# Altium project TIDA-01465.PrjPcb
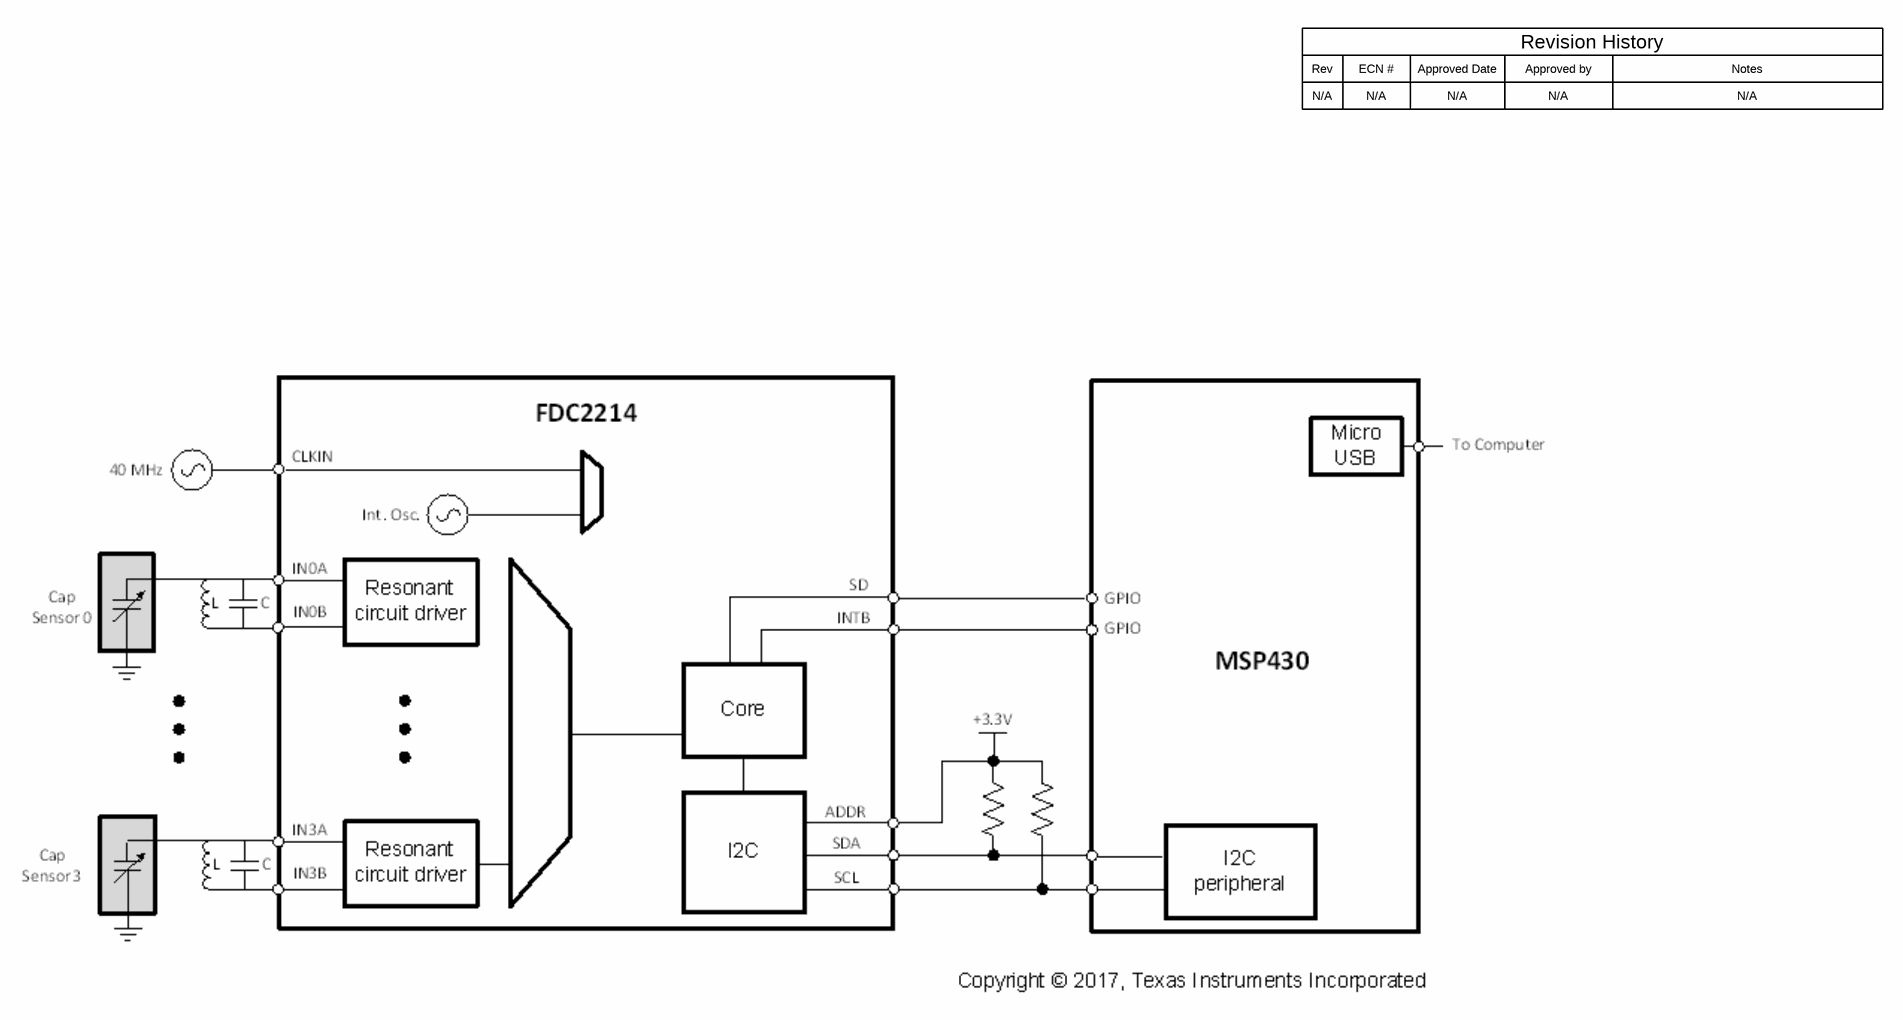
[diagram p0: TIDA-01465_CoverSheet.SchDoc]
CopyrightYear: 2016; PCB_Layout: Who did the Layout?; PCB_Rev: E1; PRJ_Customer: Public Release; PRJ_Engineer: Richard Wang; PRJ_Number: TIDA-01465; PRJ_Orderable: Orderable; PRJ_Title: Frost and ice detection; SCH_Rev: E1; TechSupport: http://www.ti.com/support; TID: TIDA-01465
3 sheets, 111 parts. Net scope: global (net labels, ports and power ports of the same name join across sheets).
Board file: TIDA-01465_PCB.PcbDoc
Sheets:
  TIDA-01465_CoverSheet.SchDoc
  TIDA-01465_Hardware.SchDoc
  TIDA-01465_Main.SchDoc

## Sheet TIDA-01465_CoverSheet.SchDoc
size 431 x 279 mm; Date: Not shown in title block; ApprovedBy: Not shown in title block; CheckedBy: Not shown in title block; Author: Not shown in title block; CompanyName: Not shown in title block; DrawnBy: Richard Wang; Engineer: Richard Wang; Organization: Not shown in title block; Address1: Not shown in title block; Address2: Not shown in title block; Address3: Not shown in title block; Address4: Not shown in title block; DocumentNumber: 1; Revision: Use project parameter SCH_Rev; SheetNumber: 1; SheetTotal: 3; PageSetup: Record=PageOptions¦CenterHorizontal=True¦CenterVertical=True¦PrintScale=1.00¦XCorrection=1.00¦YCorrection=1.00¦PrintKind=0¦BorderSize=5000000¦LeftOffset=0¦BottomOffset=0¦Orientation=2¦PaperLength=1000¦PaperWidth=1000¦Scale=100¦PaperSource=15¦PrintQuality=600¦MediaType=1¦DitherType=10¦PaperKind=Letter¦PrintScaleMode=1

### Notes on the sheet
- Rev
- N/A
- ECN #
- Approved Date
- Approved by
- Revision History
- Notes

## Sheet TIDA-01465_Hardware.SchDoc
size 431 x 279 mm; Date: Not shown in title block; ApprovedBy: Not shown in title block; CheckedBy: Not shown in title block; Author: Not shown in title block; CompanyName: Not shown in title block; Engineer: Not shown in title block; Organization: Not shown in title block; Address1: Not shown in title block; Address2: Not shown in title block; Address3: Not shown in title block; Address4: Not shown in title block; DocumentNumber: 1; Revision: Use project parameter SCH_Rev; SheetNumber: 3; SheetTotal: 3; PageSetup: Record=PageOptions¦CenterHorizontal=True¦CenterVertical=True¦PrintScale=1.00¦XCorrection=1.00¦YCorrection=1.00¦PrintKind=0¦BorderSize=5000000¦LeftOffset=0¦BottomOffset=0¦Orientation=2¦PaperLength=1000¦PaperWidth=1000¦Scale=100¦PaperSource=15¦PrintQuality=600¦MediaType=1¦DitherType=10¦PaperKind=Letter¦PrintScaleMode=1
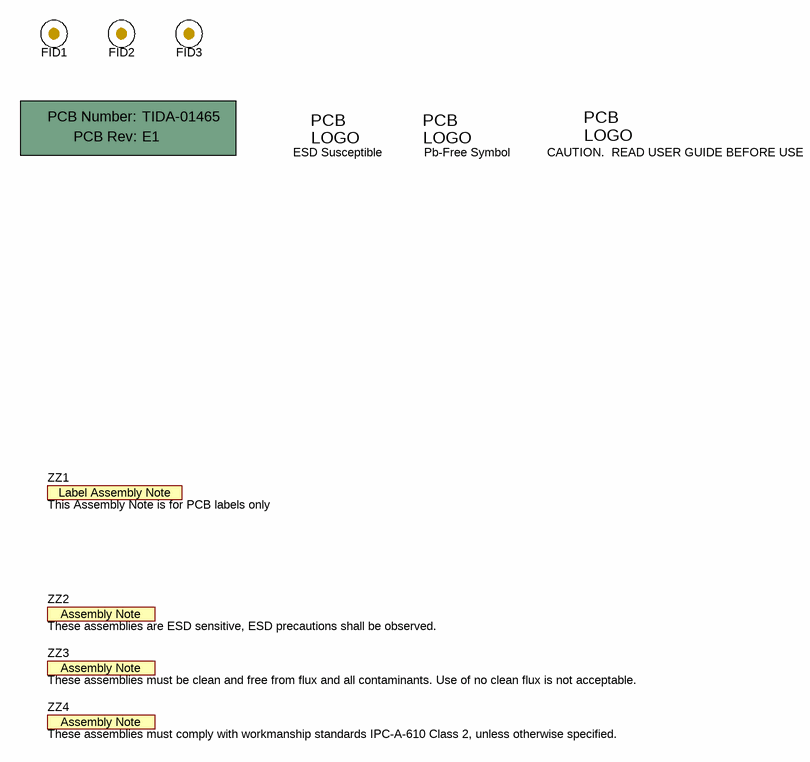
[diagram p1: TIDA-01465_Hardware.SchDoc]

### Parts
!PCB  Printed Circuit Board  (value not drawn)  (mechanical)
FID1  Fiducial  [Fiducial10-20]  (value not drawn)
FID2  Fiducial  [Fiducial10-20]  (value not drawn)
FID3  Fiducial  [Fiducial10-20]  (value not drawn)
Logo2  CAUTION.  READ USER GUIDE BEFORE USE  [IEC_Caution_Small]  (no BOM)
Logo3  Pb-Free Symbol  [Pb-Free_Overlay_Medium]  (no BOM)
Logo4  ESD Susceptible  [ESD_Overlay_Small]  (no BOM)
ZZ1  This Assembly Note is for PCB labels only  [AssemblyNoteLabel]  (no BOM)
ZZ2  These assemblies are ESD sensitive, ESD precautions shall be observed.  [AssemblyNote]  (no BOM)
ZZ3  These assemblies must be clean and free from flux and all contaminants. Use of no clean flux is not acceptable.  [AssemblyNote]  (no BOM)
ZZ4  These assemblies must comply with workmanship standards IPC-A-610 Class 2, unless otherwise specified.  [AssemblyNote]  (no BOM)

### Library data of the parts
!PCB = PCB: Manufacturer: Any; PartNumber: TIDA-01467; SymbolCreator: a0412235
FID1-FID3 = Fiducial: Fiducial mark.  There is nothing to buy or mount.; SymbolCreator: codlsc
Logo2 = IEC_Caution: IEC 61010-1 Caution Warning; SymbolCreator: a0412235
Logo3 = Pb-Free: SymbolCreator: a0412235
Logo4 = ESD_Susceptible: ESD Susceptible Symbol; SymbolCreator: a0412235
ZZ1 = AssemblyNoteLabel: SymbolCreator: a0412235
ZZ2-ZZ4 = AssemblyNote: SymbolCreator: codlsc

## Sheet TIDA-01465_Main.SchDoc
size 431 x 279 mm; Date: Not shown in title block; ApprovedBy: Not shown in title block; CheckedBy: Not shown in title block; Author: Not shown in title block; CompanyName: Not shown in title block; DrawnBy: Richard Wang; Engineer: Richard Wang; Organization: Not shown in title block; Address1: Not shown in title block; Address2: Not shown in title block; Address3: Not shown in title block; Address4: Not shown in title block; DocumentNumber: 1; Revision: Use project parameter SCH_Rev; SheetNumber: 2; SheetTotal: 3; PageSetup: Record=PageOptions¦CenterHorizontal=True¦CenterVertical=True¦PrintScale=1.00¦XCorrection=1.00¦YCorrection=1.00¦PrintKind=0¦BorderSize=5000000¦LeftOffset=0¦BottomOffset=0¦Orientation=2¦PaperLength=1000¦PaperWidth=1000¦Scale=100¦PaperSource=15¦PrintQuality=600¦MediaType=1¦DitherType=10¦PaperKind=Letter¦PrintScaleMode=1
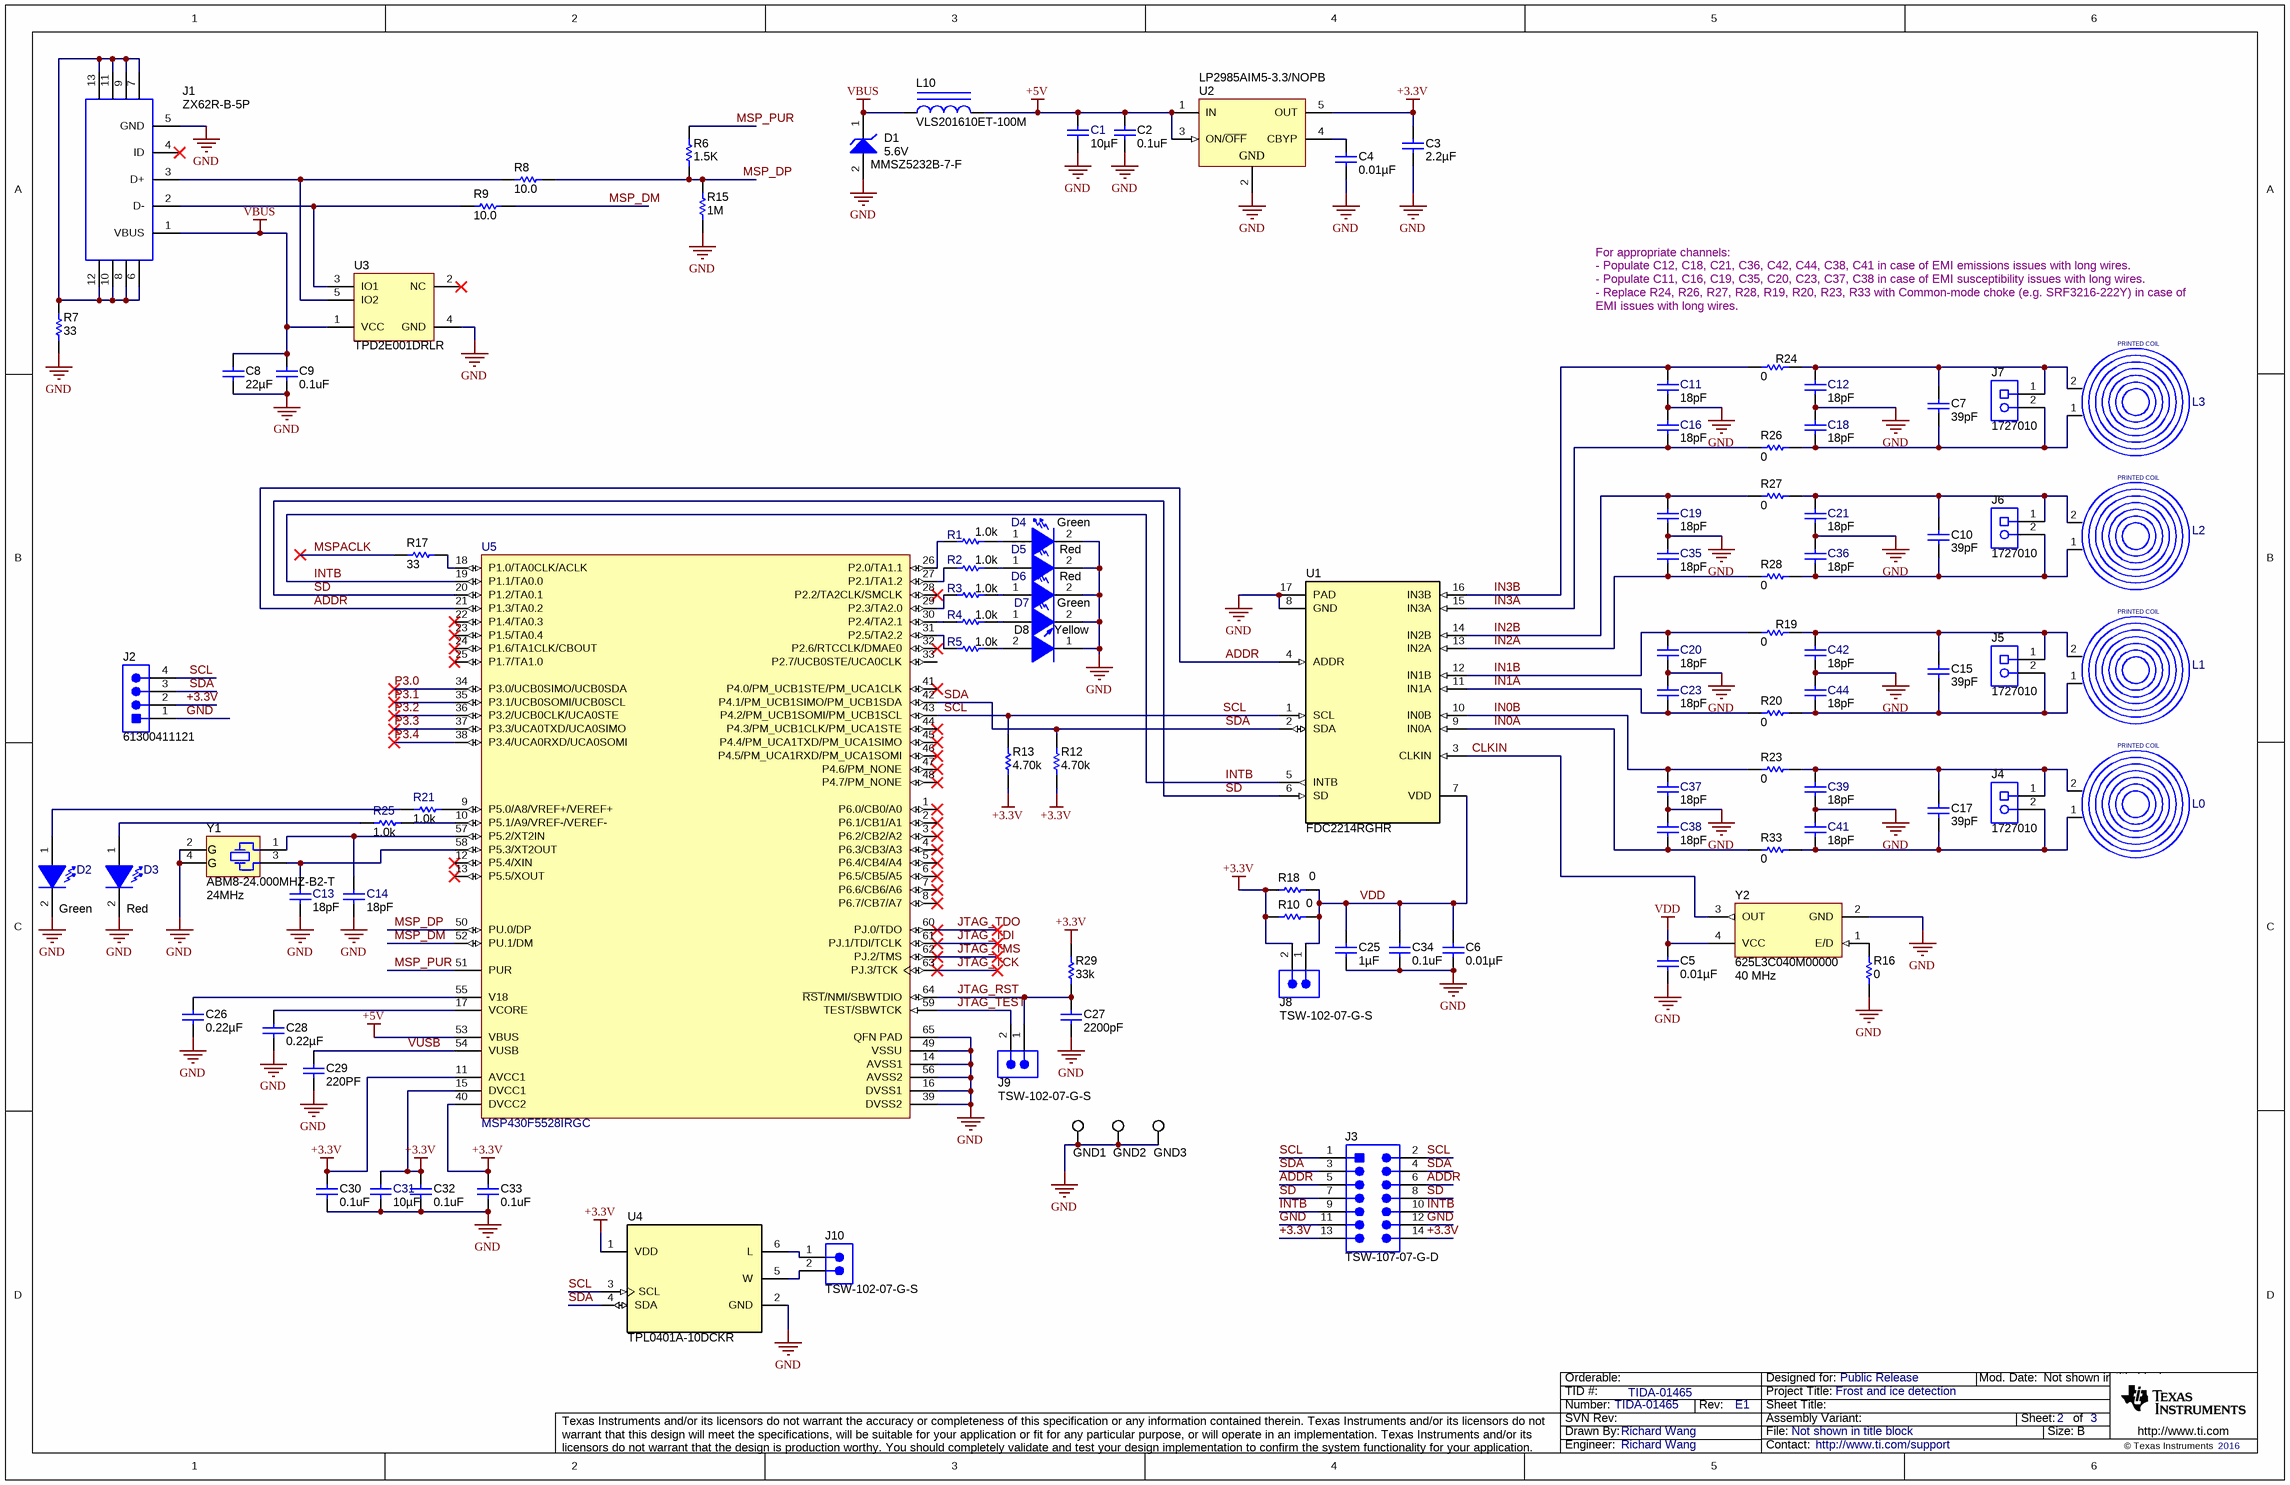
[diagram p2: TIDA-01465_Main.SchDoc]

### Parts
C1  ValueDisplayed: 10µF  [0603]  (hidden comment: C1608X5R1A106M)
C2  value 0.1uF  [0402]  (hidden comment: GRM155R71C104JA88D)
C3  ValueDisplayed: 2.2µF  [0603]  (hidden comment: C0603C225K8PACTU)
C4  ValueDisplayed: 0.01µF  [0603]  (hidden comment: C1608C0G1E103J)
C5  ValueDisplayed: 0.01µF  [0603]  (hidden comment: C1608C0G1E103J)
C6  ValueDisplayed: 0.01µF  [0402]  (hidden comment: C1005X7R1C103K)
C7  ValueDisplayed: 39pF  [0603]  (hidden comment: 06035A390JAT2A)
C8  ValueDisplayed: 22µF  [0805_HV]  (hidden comment: C2012X5R1C226K125AC)
C9  value 0.1uF  [0402]  (hidden comment: GRM155R71C104JA88D)
C10  ValueDisplayed: 39pF  [0603]  (hidden comment: 06035A390JAT2A)
C11  ValueDisplayed: 18pF  [0603]  (hidden comment: GRM1885C2A180JA01D)
C12  ValueDisplayed: 18pF  [0603]  (hidden comment: GRM1885C2A180JA01D)
C13  ValueDisplayed: 18pF  [0603]  (hidden comment: GRM1885C2A180JA01D)
C14  ValueDisplayed: 18pF  [0603]  (hidden comment: GRM1885C2A180JA01D)
C15  ValueDisplayed: 39pF  [0603]  (hidden comment: 06035A390JAT2A)
C16  ValueDisplayed: 18pF  [0603]  (hidden comment: GRM1885C2A180JA01D)
C17  ValueDisplayed: 39pF  [0603]  (hidden comment: 06035A390JAT2A)
C18  ValueDisplayed: 18pF  [0603]  (hidden comment: GRM1885C2A180JA01D)
C19  ValueDisplayed: 18pF  [0603]  (hidden comment: GRM1885C2A180JA01D)
C20  ValueDisplayed: 18pF  [0603]  (hidden comment: GRM1885C2A180JA01D)
C21  ValueDisplayed: 18pF  [0603]  (hidden comment: GRM1885C2A180JA01D)
C23  ValueDisplayed: 18pF  [0603]  (hidden comment: GRM1885C2A180JA01D)
C25  ValueDisplayed: 1µF  [0402]  (hidden comment: GRM155R61A105KE15D)
C26  ValueDisplayed: 0.22µF  [0805_HV]  (hidden comment: 08053C224JAT2A)
C27  ValueDisplayed: 2200pF  [0603]  (hidden comment: C0603X222K5RACTU)
C28  ValueDisplayed: 0.22µF  [0805_HV]  (hidden comment: 08053C224JAT2A)
C29  value 220PF  [0402]  (hidden comment: C1005C0G1H221F050BA)
C30  value 0.1uF  [0402]  (hidden comment: GRM155R71C104JA88D)
C31  ValueDisplayed: 10µF  [0603]  (hidden comment: C1608X5R1A106M)
C32  value 0.1uF  [0402]  (hidden comment: GRM155R71C104JA88D)
C33  value 0.1uF  [0402]  (hidden comment: GRM155R71C104JA88D)
C34  value 0.1uF  [0402]  (hidden comment: GRM155R71C104JA88D)
C35  ValueDisplayed: 18pF  [0603]  (hidden comment: GRM1885C2A180JA01D)
C36  ValueDisplayed: 18pF  [0603]  (hidden comment: GRM1885C2A180JA01D)
C37  ValueDisplayed: 18pF  [0603]  (hidden comment: GRM1885C2A180JA01D)
C38  ValueDisplayed: 18pF  [0603]  (hidden comment: GRM1885C2A180JA01D)
C39  ValueDisplayed: 18pF  [0603]  (hidden comment: GRM1885C2A180JA01D)
C41  ValueDisplayed: 18pF  [0603]  (hidden comment: GRM1885C2A180JA01D)
C42  ValueDisplayed: 18pF  [0603]  (hidden comment: GRM1885C2A180JA01D)
C44  ValueDisplayed: 18pF  [0603]  (hidden comment: GRM1885C2A180JA01D)
D1  MMSZ5232B-7-F  value 5.6V  [SOD-123]
D2  value Green  [LG L29K_GREEN]  (hidden comment: LG L29K-G2J1-24-Z)
D3  value Red  [SML-LX0603SRW_SuperRed]  (hidden comment: SML-LX0603SRW-TR)
D4  value Green  [LG L29K_GREEN]  (hidden comment: LG L29K-G2J1-24-Z)
D5  value Red  [SML-LX0603SRW_SuperRed]  (hidden comment: SML-LX0603SRW-TR)
D6  value Red  [SML-LX0603SRW_SuperRed]  (hidden comment: SML-LX0603SRW-TR)
D7  value Green  [LG L29K_GREEN]  (hidden comment: LG L29K-G2J1-24-Z)
D8  value Yellow  [19-21_Yellow]  (hidden comment: 19-21UYC/S530-A4/TR8)
GND1  5015  [Testpoint_Keystone_Miniature]  (value not drawn)
GND2  5015  [Testpoint_Keystone_Miniature]  (value not drawn)
GND3  5015  [Testpoint_Keystone_Miniature]  (value not drawn)
J1  ZX62R-B-5P  [Hirose_ZX62R-B-5P]
J2  61300411121  [WURTH_61300411121]
J3  TSW-107-07-G-D  [TSW-107-07-G-D]
J4  1727010  [PhoenixConact_1727010]
J5  1727010  [PhoenixConact_1727010]
J6  1727010  [PhoenixConact_1727010]
J7  1727010  [PhoenixConact_1727010]
J8  TSW-102-07-G-S  [TSW-102-07-G-S]
J9  TSW-102-07-G-S  [TSW-102-07-G-S]
J10  TSW-102-07-G-S  [TSW-102-07-G-S]
L0  PRINTED COIL  [PCBComponent_1]
L1  PRINTED COIL  [PCBComponent_1]
L2  PRINTED COIL  [PCBComponent_1]
L3  PRINTED COIL  [PCBComponent_1]
L10  VLS201610ET-100M  [VLS201610ET]
R1  value 1.0k  [0402]  (hidden comment: CRCW04021K00JNED)
R2  value 1.0k  [0402]  (hidden comment: CRCW04021K00JNED)
R3  value 1.0k  [0402]  (hidden comment: CRCW04021K00JNED)
R4  value 1.0k  [0402]  (hidden comment: CRCW04021K00JNED)
R5  value 1.0k  [0402]  (hidden comment: CRCW04021K00JNED)
R6  value 1.5K  [0402]  (hidden comment: CRCW04021K50JNED)
R7  value 33  [0603]  (hidden comment: CRCW060333R0JNEA)
R8  ValueDisplayed: 10.0  [0402]  (hidden comment: CRCW040210R0FKED)
R9  ValueDisplayed: 10.0  [0402]  (hidden comment: CRCW040210R0FKED)
R10  value 0  [0603]  (hidden comment: CRCW06030000Z0EA)
R12  value 4.70k  [0603]  (hidden comment: RC0603FR-074K7L)
R13  value 4.70k  [0603]  (hidden comment: RC0603FR-074K7L)
R15  value 1M  [0402]  (hidden comment: RC0402JR-071ML)
R16  value 0  [0603]  (hidden comment: CRCW06030000Z0EA)
R17  value 33  [0603]  (hidden comment: CRCW060333R0JNEA)
R18  value 0  [0603]  (hidden comment: CRCW06030000Z0EA)
R19  value 0  [0805_HV]  (hidden comment: CRCW08050000Z0EA)
R20  value 0  [0805_HV]  (hidden comment: CRCW08050000Z0EA)
R21  value 1.0k  [0402]  (hidden comment: CRCW04021K00JNED)
R23  value 0  [0805_HV]  (hidden comment: CRCW08050000Z0EA)
R24  value 0  [0805_HV]  (hidden comment: CRCW08050000Z0EA)
R25  value 1.0k  [0402]  (hidden comment: CRCW04021K00JNED)
R26  value 0  [0805_HV]  (hidden comment: CRCW08050000Z0EA)
R27  value 0  [0805_HV]  (hidden comment: CRCW08050000Z0EA)
R28  value 0  [0805_HV]  (hidden comment: CRCW08050000Z0EA)
R29  value 33k  [0402]  (hidden comment: CRCW040233K0JNED)
R33  value 0  [0805_HV]  (hidden comment: CRCW08050000Z0EA)
U1  FDC2214RGHR  [RGH0016A]
U2  LP2985AIM5-3.3/NOPB  [MF05A_N]
U3  TPD2E001DRLR  [DRL0005A]
U4  TPL0401A-10DCKR  [DCK0006A_N]
U5  MSP430F5528IRGC  [RGC0064B]
Y1  ABM8-24.000MHZ-B2-T  Frequency: 24MHz  [XTAL_ABM8]
Y2  625L3C040M00000  Frequency: 40 MHz  [OSC_CTS_625]

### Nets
+3.3V: C3.1 C30.1 C31.1 C32.1 C33.1 J2.2 J3.13 J3.14 J8.2 R10.1 R12.1 R13.1 R18.1 R29.1 U2.5(OUT) U4.1(VDD) U5.11(AVCC1) U5.15(DVCC1) U5.40(DVCC2)
+5V: C1.1 C2.1 L10.2 U2.1(IN) U2.3(ON/~{OFF}) U5.53(VBUS)
GND: C1.2 C2.2 C3.2 C4.2 C5.2 C6.2 C8.2 C9.2 C11.1 C12.1 C13.1 C14.1 C16.2 C18.2 C19.1 C20.1 C21.1 C23.2 C25.2 C26.2 C27.1 C28.2 C29.2 C30.2 C31.2 C32.2 C33.2 C34.2 C35.2 C36.2 C37.1 C38.2 C39.1 C41.2 C42.1 C44.2 D1.2(A) D2.2(K) D3.2(K) D4.2(K) D5.2(K) D6.2(K) D7.2(K) D8.1(K) GND1.1 GND2.1 GND3.1 J1.5(GND) J2.1 J3.11 J3.12 R7.1 R15.1 R16.1 U1.8(GND) U1.17(PAD) U2.2(GND) U3.4(GND) U4.2(GND) U5.14(AVSS1) U5.16(DVSS1) U5.39(DVSS2) U5.49(VSSU) U5.56(AVSS2) U5.65(QFN_PAD) Y1.2(GND) Y1.4(GND) Y2.2(GND)
VBUS: C8.1 C9.1 D1.1(K) J1.1(VBUS) L10.1 U3.1(VCC)
VDD: C5.1 C6.1 C25.1 C34.1 J8.1 R10.2 R18.2 U1.7(VDD) Y2.4(VCC)
ADDR: J3.5 J3.6 U1.4(ADDR) U5.21(P1.3/TA0.2)
CLKIN: U1.3(CLKIN) Y2.3(OUT)
IN0A: C38.1 R33.1 U1.9(IN0A)
IN0B: C37.2 R23.1 U1.10(IN0B)
IN1A: C23.1 R20.1 U1.11(IN1A)
IN1B: C20.2 R19.1 U1.12(IN1B)
IN2A: C35.1 R28.1 U1.13(IN2A)
IN2B: C19.2 R27.1 U1.14(IN2B)
IN3A: C16.1 R26.1 U1.15(IN3A)
IN3B: C11.2 R24.1 U1.16(IN3B)
INTB: J3.9 J3.10 U1.5(INTB) U5.19(P1.1/TA0.0)
JTAG_RST: C27.2 J9.1 R29.2 U5.64(~{RST}/NMI/SBWTDIO)
JTAG_TCK: U5.63(PJ.3/TCK)
JTAG_TDI: U5.61(PJ.1/TDI/TCLK)
JTAG_TDO: U5.60(PJ.0/TDO)
JTAG_TEST: J9.2 U5.59(TEST/SBWTCK)
JTAG_TMS: U5.62(PJ.2/TMS)
MSP_DM: R9.2 U5.52(PU.1/DM)
MSP_DP: R6.1 R8.2 R15.2 U5.50(PU.0/DP)
MSP_PUR: R6.2 U5.51(PUR)
MSPACLK: R17.2
P3.0: U5.34(P3.0/UCB0SIMO/UCB0SDA)
P3.1: U5.35(P3.1/UCB0SOMI/UCB0SCL)
P3.2: U5.36(P3.2/UCB0CLK/UCA0STE)
P3.3: U5.37(P3.3/UCA0TXD/UCA0SIMO)
P3.4: U5.38(P3.4/UCA0RXD/UCA0SOMI)
SCL: J2.4 J3.1 J3.2 R13.2 U1.1(SCL) U4.3(SCL) U5.43(P4.2/PM_UCB1SOMI/PM_UCB1SCL)
SD: J3.7 J3.8 U1.6(SD) U5.20(P1.2/TA0.1)
SDA: J2.3 J3.3 J3.4 R12.2 U1.2(SDA) U4.4(SDA) U5.42(P4.1/PM_UCB1SIMO/PM_UCB1SDA)
VUSB: C29.1 U5.54(VUSB)
NetC4_1: C4.1 U2.4(CBYP)
NetC7_1: C7.1 C18.1 J7.2 L3.1(.) R26.2
NetC7_2: C7.2 C12.2 J7.1 L3.2(.) R24.2
NetC10_1: C10.1 C36.1 J6.2 L2.1(.) R28.2
NetC10_2: C10.2 C21.2 J6.1 L2.2(.) R27.2
NetC13_2: C13.2 U5.58(P5.3/XT2OUT) Y1.3
NetC14_2: C14.2 U5.57(P5.2/XT2IN) Y1.1
NetC15_1: C15.1 C44.1 J5.2 L1.1(.) R20.2
NetC15_2: C15.2 C42.2 J5.1 L1.2(.) R19.2
NetC17_1: C17.1 C41.1 J4.2 L0.1(.) R33.2
NetC17_2: C17.2 C39.2 J4.1 L0.2(.) R23.2
NetC26_1: C26.1 U5.55(V18)
NetC28_1: C28.1 U5.17(VCORE)
NetD2_1: D2.1(A) R21.2
NetD3_1: D3.1(A) R25.2
NetD4_1: D4.1(A) R1.1
NetD5_1: D5.1(A) R2.1
NetD6_1: D6.1(A) R3.1
NetD7_1: D7.1(A) R4.1
NetD8_2: D8.2(A) R5.1
NetJ1_2: J1.2(D-) R9.1 U3.3(IO1)
NetJ1_3: J1.3(D+) R8.1 U3.5(IO2)
NetJ1_6: J1.6 J1.7 J1.8 J1.9 J1.10 J1.11 J1.12 J1.13 R7.2
NetJ10_1: J10.1 U4.6(L)
NetJ10_2: J10.2 U4.5(W)
NetR1_2: R1.2 U5.26(P2.0/TA1.1)
NetR2_2: R2.2 U5.27(P2.1/TA1.2)
NetR3_2: R3.2 U5.29(P2.3/TA2.0)
NetR4_2: R4.2 U5.30(P2.4/TA2.1)
NetR5_2: R5.2 U5.31(P2.5/TA2.2)
NetR16_2: R16.2 Y2.1(E/D)
NetR17_1: R17.1 U5.18(P1.0/TA0CLK/ACLK)
NetR21_1: R21.1 U5.9(P5.0/A8/VREF+/VEREF+)
NetR25_1: R25.1 U5.10(P5.1/A9/VREF-/VEREF-)

Not connected (* = marked no-connect by the designer): J1 4(ID)*; U3 2(NC)*; U5 1(P6.0/CB0/A0)* 2(P6.1/CB1/A1)* 3(P6.2/CB2/A2)* 4(P6.3/CB3/A3)* 5(P6.4/CB4/A4)* 6(P6.5/CB5/A5)* 7(P6.6/CB6/A6)* 8(P6.7/CB7/A7)* 12(P5.4/XIN)* 13(P5.5/XOUT)* 22(P1.4/TA0.3)* 23(P1.5/TA0.4)* 24(P1.6/TA1CLK/CBOUT)* 25(P1.7/TA1.0)* 28(P2.2/TA2CLK/SMCLK)* 32(P2.6/RTCCLK/DMAE0)* 33(P2.7/UCB0STE/UCA0CLK) 41(P4.0/PM_UCB1STE/PM_UCA1CLK)* 44(P4.3/PM_UCB1CLK/PM_UCA1STE)* 45(P4.4/PM_UCA1TXD/PM_UCA1SIMO)* 46(P4.5/PM_UCA1RXD/PM_UCA1SOMI)* 47(P4.6/PM_NONE)* 48(P4.7/PM_NONE)*

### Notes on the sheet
- For appropriate channels:
  - Populate C12, C18, C21, C36, C42, C44, C38, C41 in case of EMI emissions issues with long wires.
  - Populate C11, C16, C19, C35, C20, C23, C37, C38 in case of EMI susceptibility issues with long wires.
  - Replace R24, R26, R27, R28, R19, R20, R23, R33 with Common-mode choke (e.g. SRF3216-222Y) in case of EMI issues with long wires.

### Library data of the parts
C1 C31 = C1608X5R1A106M: CAP, CERM, 10uF, 10V, +/-20%, X5R, 0603; Manufacturer: TDK; Polarized: N; CompType: Capacitor; U/M: EA; Cap_F: 0.00001; Tolerance_%: 20; ESR_Ohm: 0.0078; Value1: 0.0078 ohm; VDC_V: 10; IRMS_A: 1.85; TaMin_C: -55; TaMax_C: 85
C2 C9 C30 C32-C34 = 0402YC132KAT2A: CAP CER 0.1UF 16V 5% X7R 0402; Manufacturer: Murata Electronics North America; Polarized: N; CompType: Capacitor; U/M: EA; Cap_F: 0.0000000013; Tolerance_%: 10; VDC_V: 16; TaMin_C: -55; TaMax_C: 125
C3 = C0603C225K8PACTU: CAP, CERM, 2.2uF, 10V, +/-10%, X5R, 0603; Manufacturer: Kemet; Polarized: N; CompType: Capacitor; U/M: EA; Cap_F: 0.0000022; Tolerance_%: 10; Value1: Unknown; TaMin_C: -55; TaMax_C: 85
C4 C5 = C1608C0G1E103J: CAP, CERM, 0.01uF, 25V, +/-5%, C0G/NP0, 0603; Manufacturer: TDK; Polarized: N; CompType: Capacitor; U/M: EA; Cap_F: 0.00000001; Tolerance_%: 5; VDC_V: 25; TaMin_C: -55; TaMax_C: 125
C6 = C1005X7R1C103K: CAP, CERM, 0.01 µF, 16 V, +/- 10%, X7R, 0402; Manufacturer: TDK; Polarized: N; CompType: Capacitor; Value: 0.01uF; U/M: EA; Cap_F: 0.00000001; Tolerance_%: 10; ESR_ohm: 0.0623; Value1: 0.0623 ohm; VDC_V: 16; Value2: 16V; TaMin_C: -55; TaMax_C: 125
C7 C10 C15 C17 = 06035A390JAT2A: CAP, CERM, 39 pF, 50 V, +/- 5%, C0G/NP0, 0603; Manufacturer: AVX; Polarized: N; CompType: Capacitor; Value: 39pF; U/M: EA; Cap_F: 0.000000000039; Tolerance_%: 5; ESR_ohm: 0.191; Value1: 0.191 ohm; VDC_V: 50; Value2: 50V; TaMin_C: -55; TaMax_C: 125; SizeArea_mm2: 1.28; SizeAreaWB_mm2: 4.68; SizeX_mm: 1.6; SizeY_mm: 0.8; SizeZ_mm: 1; AEC Category: Q200
C8 = C2012X5R1C226K125AC: CAP, CERM, 22uF, 16V, +/-10%, X5R, 0805; Manufacturer: TDK; Polarized: N; CompType: Capacitor; U/M: EA; Cap_F: 0.000022; Tolerance_%: 10; Value1: Unknown; VDC_V: 16; TaMin_C: -55; TaMax_C: 85; Cap_Case: 0805
C11-C14 C16 C18-C21 C23 C35-C39 C41 C42 C44 = GRM1885C2A180JA01D: CAP, CERM, 18pF, 100V, +/-5%, C0G/NP0, 0603; Manufacturer: MuRata; Polarized: N; CompType: Capacitor; U/M: EA; Cap_F: 0.000000000018; Tolerance_%: 5; Value1: Unknown; VDC_V: 100; TaMin_C: -55; TaMax_C: 125
C25 = GRM155R61A105KE15D: CAP, CERM, 1uF, 10V, +/-10%, X5R, 0402; Manufacturer: MuRata; Polarized: N; CompType: Capacitor; U/M: EA; Cap_F: 0.000001; Tolerance_%: 10; Value1: Unknown; TaMin_C: -55; TaMax_C: 85
C26 C28 = 08053C224JAT2A: CAP, CERM, 0.22 µF, 25 V, +/- 5%, X7R, 0805; Manufacturer: AVX; Polarized: N; CompType: Capacitor; Value: 0.22uF; U/M: EA; Cap_F: 0.00000022; Tolerance_%: 5; ESR_ohm: 0.016; Value1: 0.016 ohm; VDC_V: 25; Value2: 25V; TaMin_C: -55; TaMax_C: 125; Cap_Case: 0805
C27 = C0603X222K5RACTU: CAP, CERM, 2200pF, 50V, +/-10%, X7R, 0603; Manufacturer: Kemet; Polarized: N; CompType: Capacitor; U/M: EA; Cap_F: 0.0000000022; Tolerance_%: 10; VDC_V: 50; TaMin_C: -55; TaMax_C: 125
C29 = 0402YC132KAT2A: CAP CER 220PF 50V 1% NP0 0402; Manufacturer: TDK Corporation; Polarized: N; CompType: Capacitor; U/M: EA; Cap_F: 0.0000000013; Tolerance_%: 10; VDC_V: 16; TempCo: X7R; TaMin_C: -55; TaMax_C: 125
D1 = MMSZ5232B-7-F: Diode, Zener, 5.6V, 500mW, SOD-123; Manufacturer: Diodes Inc.; U/M: EA; Power_W: 0.5; Vz_V: 5.6; Value1: 0.5W; RJA_CperW: 350
D2 D4 D7 = LG L29K-G2J1-24-Z: LED, Green, SMD; Manufacturer: OSRAM; Vf_V: 1.7; Value2: 1.7V; Io_A: 0.002; Tjmax_C: 110; Value1: W; U/M: EA
D3 D5 D6 = SML-LX0603SRW-TR: LED, Super Red, SMD; Manufacturer: Lumex; Vf_V: 1.7; Value2: 1.7V; Io_A: 0.02; Value1: W; U/M: EA
D8 = 19-21UYC/S530-A4/TR8: LED, Yellow, SMD; Manufacturer: Everlight; Type: AlInGaP; Vf_V: 2; Value2: 2V; Io_A: 0.02; Vr_V: 5; Ir_A: 1e-005; Tjmax_C: 85; Value1: W; Angle: 100; U/M: EA
GND1-GND3 = 5015: Test Point, Miniature, SMT; Manufacturer: Keystone; CompType: Test Point Loop; U/M: EA
J1 = ZX62R-B-5P: Connector, Receptacle, Micro-USB Type B, SMT; Manufacturer: Hirose Electric Co. Ltd.; SymbolCreator: a0799628; U/M: EA
J2 = 61300411121: Header, 2.54 mm, 4x1, Gold, TH; Manufacturer: Wurth Elektronik; SymbolCreator: a0412235
J3 = TSW-107-07-G-D: Header, 100mil, 7x2, Gold, TH; Manufacturer: Samtec; SymbolCreator: a0412235; U/M: EA
J4-J7 = 1727010: Conn Term Block, 2POS, 3.81mm, TH; Manufacturer: Phoenix Contact; SymbolCreator: a0412235; CompType: Terminal Block; U/M: EA; Value: 2x1
J8-J10 = TSW-102-07-G-S: Header, TH, 100mil, 2x1, Gold plated, 230 mil above insulator; Manufacturer: Samtec, Inc.; SymbolCreator: a0412235; U/M: EA
L0-L3 = PRINTED COIL: 8.2MM 2-layer Coil 3.5uH
L10 = VLS201610ET-100M: Inductor, Shielded, Ferrite, 10 µH, 0.4 A, 1.38 ohm, SMD; Manufacturer: TDK; Value: 10uH; Ind_H: 10.0E-6; ValueDisplayed: 10µH; Imax_A: 0.4; Irms: 0.42A @ 40C rise; Isat: 0.4A @ 30% inductance drop; DCR_ohm: 1.38; Value2: 0.4A
R1-R5 R21 R25 = CRCW04021K00JNED: RES, 1.0k ohm, 5%, 0.063W, 0402; Manufacturer: Vishay-Dale; CompType: Resistor; Res_ohm: 1000; Value_Code: 1k00; Tolerance_%: 5; Power_W: 0.063; VDC_V: 50; TempCo: 200 ppm/C; EIA_Code: E24; U/M: EA
R6 = CRCW040233K0JNED: RES 1.5K OHM 1/16W 5% 0402 SMD; Manufacturer: Vishay Dale; CompType: Resistor; Res_ohm: 33000; Value_Code: 33k0; Tolerance_%: 5; Power_W: 0.063; Value2: 0.063W; VDC_V: 50; TempCo: 200 ppm/C; EIA_Code: E24; U/M: EA
R7 R17 = CRCW060333R0JNEA: RES, 33 ohm, 5%, 0.1W, 0603; Manufacturer: Vishay-Dale; CompType: Resistor; Value_Code: 33R0; Tolerance_%: 5; Power_W: 0.1; VDC_V: 75; TempCo: 200 ppm/C; EIA_Code: E24; U/M: EA
R8 R9 = CRCW040210R0FKED: RES, 10.0, 1%, 0.063 W, 0402; Manufacturer: Vishay-Dale; CompType: Resistor; Value: 10.0; Res_ohm: 10; Value_Code: 10R0; Tolerance_%: 1; Power_W: 0.063; Value2: 0.063W; VDC_V: 50; TempCo: 100 ppm/C; EIA_Code: E96; U/M: EA
R10 R16 R18 = CRCW06030000Z0EA: RES, 0 ohm, 5%, 0.1W, 0603; Manufacturer: Vishay-Dale; CompType: Resistor; Value_Code: 0000; Tolerance_%: 5; Power_W: 0.1; VDC_V: 75; TempCo: 200 ppm/C; EIA_Code: E24; U/M: EA
R12 R13 = RC0603FR-074K7L: RES, 4.70k ohm, 1%, 0.1W, 0603; Manufacturer: Yageo America; CompType: Resistor; Res_ohm: 4700; Value_Code: 4k70; Tolerance_%: 1; Power_W: 0.1; VDC_V: 150; TempCo: 200 ppm/C; U/M: EA
R15 = CRCW040233K0JNED: RES,1M ohm, 5%, 0.063W, 0402; Manufacturer: Yageo; CompType: Resistor; Res_ohm: 33000; Value_Code: 33k0; Tolerance_%: 5; Power_W: 0.063; VDC_V: 50; TempCo: 200 ppm/C; EIA_Code: E24; U/M: EA
R19 R20 R23 R24 R26-R28 R33 = CRCW08050000Z0EA: RES, 0 ohm, 5%, 0.125W, 0805; Manufacturer: Vishay-Dale; CompType: Resistor; Value_Code: 0000; Tolerance_%: 5; Power_W: 0.125; VDC_V: 150; TempCo: 200 ppm/C; EIA_Code: E24; U/M: EA
R29 = CRCW040233K0JNED: RES, 33k ohm, 5%, 0.063W, 0402; Manufacturer: Vishay-Dale; CompType: Resistor; Res_ohm: 33000; Value_Code: 33k0; Tolerance_%: 5; Power_W: 0.063; VDC_V: 50; TempCo: 200 ppm/C; EIA_Code: E24; U/M: EA
U1 = FDC2214RGHR: Noise-immune Capacitive Sensing Solution for Proximity Sensing, RGH0016A (WQFN-16); Manufacturer: Texas Instruments; SymbolCreator: a0411947; SizeArea_mm2: 16; SizeAreaWB_mm2: 25; SizeX_mm: 4; SizeZ_mm: 0.8; CompType: IC; U/M: EA
U2 = LP2985AIM5-3.3/NOPB: Micropower 150 mA Low-Noise Ultra Low-Dropout Regulator, 5-pin SOT-23, Pb-Free; Manufacturer: Texas Instruments; PackageTopMarking: L0RA*XTT; PowerWise: N; CompType: LDO IC
U3 = TPD2E001DRLR: Low-Capacitance + / - 15 kV ESD-Protection Array for High-Speed Data Interfaces, 2 Channels, -40 to +85 degC, 5-pin SOT (DRL), Green (RoHS & no Sb/Br); Manufacturer: Texas Instruments; Alternate Manufacturer: None; Alternate PartNumber: Equivalent; Breakdown Voltage(Min)(V): 11; IEC 61000-4-2 Air-Gap(+/- kV): 15; IEC 61000-4-2 Contact(+/- kV): 8; IO Capacitance(Typ)(pF): 1.5; IO Leakage Current(nA): 1; SubFamily: ESD Solution; USB High Speed: TRUE
U4 = TPL0401C-50DCKR: 128 TAPS Single Channel Digital Potentiometer with I2C Interface, DCK0006A (SOT-6); Manufacturer: Texas Instruments; SymbolCreator: a0411947; SizeArea_mm2: 4.2; SizeAreaWB_mm2: 9.3; SizeX_mm: 2.1; SizeY_mm: 2; SizeZ_mm: 1.1; CompType: IC; U/M: EA
U5 = MSP430F5528IRGC: Mixed Signal MicroController, RGC0064B; Manufacturer: Texas Instruments; Alternate Manufacturer: None; ADC: 12-bit SAR; ADC Channels: 16; Brown Out Reset: Yes; DMA: 3; Eco-Plan: Green (RoHS & no Sb/Br); Flash(KB): 128; Frequency(MHz): 25; GPIO: 47; Multiplier: 32x32; SRAM(B): 8192; SubFamily: 5 Series; Timers - 16-bit: 4; USB: 1; USCI_A (UART/LIN/IrDA/SPI): 2; SymbolCreator: Altium/a0412235; CompType: IC; U/M: EA
Y1 = ABM8-24.000MHZ-B2-T: Crystal, 24.000MHz, 18pF, SMD; Manufacturer: Abracon Corportation; SymbolCreator: a0412235; U/M: EA; TaMin_C: -20; TaMax_C: 70; Frequency Stability: ±50ppm
Y2 = 625L3C040M00000: OSC, 40 MHz, 3.3 V, SMD; Manufacturer: CTS Electrocomponents; SymbolCreator: a0411947; CompType: Oscillator; U/M: EA; TaMin_C: -20; TaMax_C: 70; Frequency Stability: ±50ppm

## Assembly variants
001: not fitted FID1 FID2 FID3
